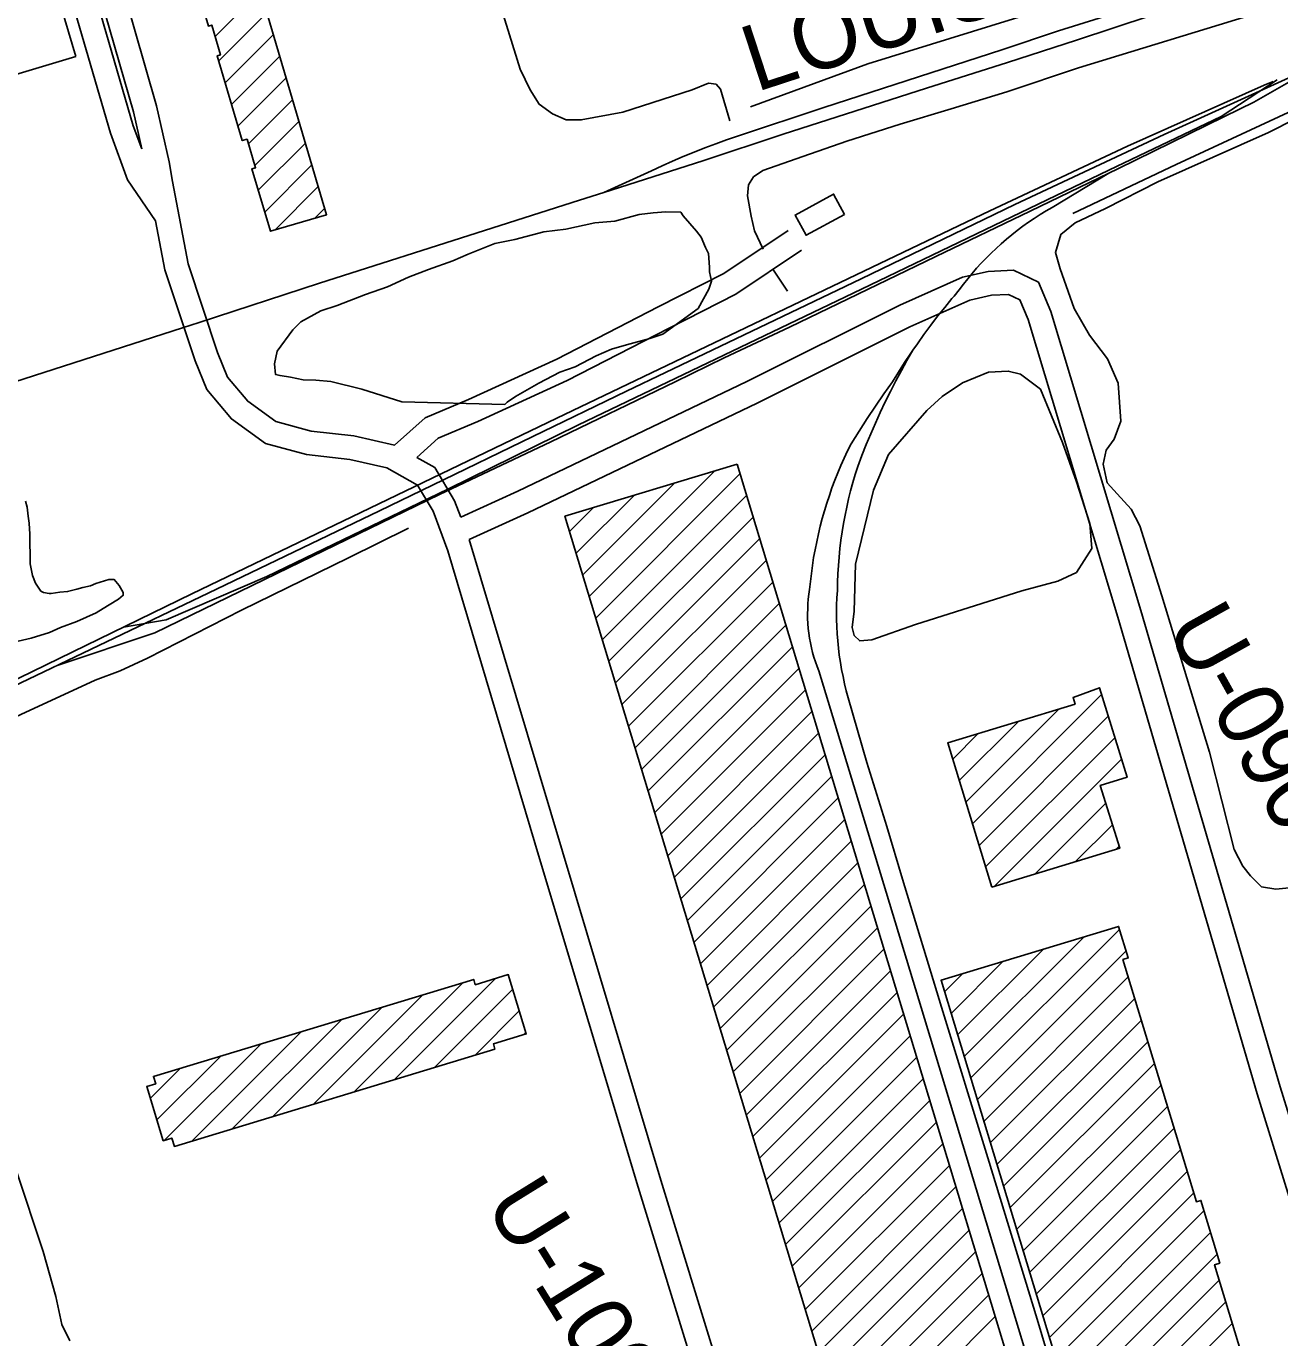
# Model space of a CAD drawing. Extents: x 3598634 to 3636690, y 517270 to 542944.
# Drawn here: x 3608299 to 3609873, y 535647 to 537294 of the extents above; entities that cross this region are included whole.
import ezdxf

# ---------------------------------------------------------------- set-up
doc = ezdxf.new("R2010")
doc.units = 0
for name, color, linetype in [('V-BLDG-OTLN', 7, 'Continuous'), ('V-RAIL-IDEN', 7, 'Continuous'), ('V-RAIL-TRAK', 7, 'Continuous'), ('V-RIVR-RANG-IDEN', 7, 'Continuous'), ('V-ROAD-CNTR', 7, 'Continuous'), ('V-SITE-VEGE', 7, 'Continuous'), ('V-TOPO-SHOR', 7, 'Continuous')]:
    doc.layers.add(name, color=color, linetype=linetype)

msp = doc.modelspace()

# ---------------------------------------------------------------- linework, layer by layer
at = {"layer": 'V-BLDG-OTLN'}
for p, q in [((3608536.4, 537281.6), (3608593.5, 537338.7)), ((3608541, 537250.8), (3608601.6, 537311.4)), ((3608549.1, 537223.5), (3608609.6, 537284.1)), ((3608557.1, 537196.2), (3608617.7, 537256.8)), ((3608565.2, 537168.9), (3608625.7, 537229.5)), ((3608578.3, 537146.8), (3608633.8, 537202.2)), ((3608586.4, 537119.5), (3608641.8, 537174.9)), ((3608590.7, 537088.4), (3608649.9, 537147.6)), ((3608598.8, 537061.1), (3608657.9, 537120.3)), ((3608611.5, 537038.5), (3608666, 537093)), ((3608661.6, 537053.3), (3608674, 537065.7)), ((3609006.2, 536578.3), (3609163.8, 536735.9)), ((3609014.4, 536551.1), (3609195.4, 536732.1)), ((3608989.8, 536632.6), (3609062.4, 536705.2)), ((3608998, 536605.4), (3609113.1, 536720.5)), ((3609022.7, 536524), (3609203.7, 536705)), ((3608981.6, 536659.7), (3609011.7, 536689.8)), ((3609030.9, 536496.9), (3609211.9, 536677.9)), ((3609039.1, 536469.7), (3609220.1, 536650.7)), ((3609047.3, 536442.6), (3609228.3, 536623.6)), ((3609055.5, 536415.5), (3609236.5, 536596.4)), ((3609063.7, 536388.3), (3609244.7, 536569.3)), ((3609072, 536361.2), (3609253, 536542.2)), ((3609080.2, 536334), (3609261.2, 536515)), ((3609088.4, 536306.9), (3609269.4, 536487.9)), ((3609096.6, 536279.8), (3609277.6, 536460.8)), ((3609487.3, 536292.7), (3609649.4, 536454.9)), ((3609104.8, 536252.6), (3609285.8, 536433.6)), ((3609479, 536319.8), (3609596.2, 536437)), ((3609495.5, 536265.6), (3609657.8, 536427.9)), ((3609470.8, 536346.9), (3609545.4, 536421.5)), ((3609113.1, 536225.5), (3609294, 536406.5)), ((3609462.5, 536374), (3609494.5, 536406)), ((3609503.8, 536238.5), (3609666.1, 536400.8)), ((3609121.3, 536198.4), (3609302.3, 536379.3)), ((3609514.5, 536213.9), (3609674.4, 536373.8)), ((3609129.5, 536171.2), (3609310.5, 536352.2)), ((3609137.7, 536144.1), (3609318.7, 536325.1)), ((3609565.4, 536229.4), (3609654.6, 536318.7)), ((3609145.9, 536116.9), (3609326.9, 536297.9)), ((3609616.2, 536244.9), (3609662.9, 536291.6)), ((3609154.1, 536089.8), (3609335.1, 536270.8)), ((3609667.1, 536260.4), (3609671.3, 536264.6)), ((3609162.4, 536062.7), (3609343.3, 536243.7)), ((3609170.6, 536035.5), (3609351.6, 536216.5)), ((3609178.8, 536008.4), (3609359.8, 536189.4)), ((3609187, 535981.2), (3609368, 536162.2)), ((3609476.8, 536000.3), (3609626.9, 536150.4)), ((3609485, 535973.2), (3609671.9, 536160.1)), ((3609195.2, 535954.1), (3609376.2, 536135.1)), ((3609468.6, 536027.5), (3609576.2, 536135)), ((3609493.3, 535946.1), (3609680.2, 536133)), ((3609460.4, 536054.6), (3609525.4, 536119.6)), ((3608761.2, 535971.2), (3608888.3, 536098.2)), ((3609203.4, 535927), (3609384.4, 536108)), ((3609452.1, 536081.7), (3609474.7, 536104.3)), ((3609501.5, 535918.9), (3609682.8, 536100.3)), ((3608710.5, 535955.7), (3608848.1, 536093.4)), ((3608812, 535986.6), (3608910.2, 536084.8)), ((3609211.7, 535899.8), (3609392.6, 536080.8)), ((3608608.9, 535924.9), (3608746.6, 536062.6)), ((3608659.7, 535940.3), (3608797.3, 536078)), ((3609509.7, 535891.8), (3609691.1, 536073.1)), ((3608558.1, 535909.5), (3608695.8, 536047.1)), ((3608862.8, 536002), (3608918.4, 536057.6)), ((3609219.9, 535872.7), (3609400.9, 536053.7)), ((3609517.9, 535864.7), (3609699.3, 536046)), ((3608507.4, 535894.1), (3608645, 536031.7)), ((3608924, 536027.9), (3608926.7, 536030.5)), ((3608473.1, 535895.2), (3608594.2, 536016.3)), ((3609228.1, 535845.6), (3609409.1, 536026.5)), ((3609526.2, 535837.5), (3609707.5, 536018.9)), ((3608463.4, 535920.8), (3608543.5, 536000.9)), ((3609236.3, 535818.4), (3609417.3, 535999.4)), ((3608455.2, 535947.9), (3608492.7, 535985.5)), ((3609534.4, 535810.4), (3609715.7, 535991.7)), ((3609244.5, 535791.3), (3609425.5, 535972.3)), ((3609542.6, 535783.3), (3609724, 535964.6)), ((3609252.7, 535764.1), (3609433.7, 535945.1)), ((3609550.9, 535756.2), (3609732.2, 535937.5)), ((3609261, 535737), (3609442, 535918)), ((3609559.1, 535729), (3609740.4, 535910.4)), ((3609269.2, 535709.9), (3609450.2, 535890.9)), ((3609567.3, 535701.9), (3609748.6, 535883.2)), ((3609277.4, 535682.7), (3609458.4, 535863.7)), ((3609575.5, 535674.8), (3609756.9, 535856.1)), ((3609285.6, 535655.6), (3609466.6, 535836.6)), ((3609583.8, 535647.6), (3609765.1, 535829)), ((3609293.8, 535628.5), (3609474.8, 535809.4)), ((3609592, 535620.5), (3609777.9, 535806.5)), ((3609302.1, 535601.3), (3609483, 535782.3)), ((3609600.2, 535593.4), (3609786.2, 535779.4)), ((3609310.3, 535574.2), (3609491.3, 535755.2)), ((3609608.4, 535566.2), (3609794.4, 535752.2)), ((3609318.5, 535547), (3609499.5, 535728)), ((3609616.7, 535539.1), (3609797, 535719.5)), ((3609326.7, 535519.9), (3609507.7, 535700.9)), ((3609624.9, 535512), (3609805.3, 535692.4)), ((3609334.9, 535492.8), (3609515.9, 535673.8)), ((3609633.1, 535484.9), (3609813.5, 535665.2))]:
    msp.add_line(p, q, dxfattribs=at)
for points in [[(3608721.3, 537478.3), (3608557, 537429.9), (3608573.8, 537373.1), (3608582.6, 537375.7), (3608676.4, 537057.6), (3608605.9, 537036.9), (3608582.7, 537115.5), (3608587.2, 537116.8), (3608576.6, 537152.6), (3608570.5, 537150.8), (3608539.1, 537257.3), (3608543.2, 537258.5), (3608532.2, 537295.9), (3608528, 537294.7), (3608493.8, 537410.6), (3608511.1, 537415.7), (3608488.5, 537492.2), (3608533.9, 537505.6), (3608534.7, 537503), (3608632.8, 537532), (3608631.7, 537535.7), (3608697.3, 537555.1)], [(3608361.5, 537256.3), (3608179.9, 537202), (3608146.2, 537314.8), (3608328.2, 537369.3)], [(3609326.7, 537058.2), (3609278.4, 537031.9), (3609264.6, 537057.3), (3609312.9, 537083.6)], [(3609191.7, 536744.3), (3609664, 535184.5), (3609504.1, 535136.1), (3609507.4, 535125.2), (3609451.4, 535108.2), (3608975.7, 536678.9)], [(3609511.5, 536213), (3609456.3, 536394.4), (3609616.2, 536443.1), (3609613.7, 536451.2), (3609646.8, 536463.6), (3609681.3, 536351.2), (3609647.8, 536340.9), (3609672.1, 536261.9)], [(3609679.8, 535330.8), (3609447.8, 536096.1), (3609670.8, 536163.7), (3609682.8, 536124.2), (3609676.2, 536122.1), (3609768.4, 535818), (3609774, 535819.7), (3609797.8, 535740.9), (3609791.2, 535738.9), (3609883.3, 535435.1), (3609890.8, 535437.4), (3609902.6, 535398.4)], [(3608887.8, 536009.6), (3608485.3, 535887.4), (3608482.1, 535897.9), (3608471.3, 535894.6), (3608450.7, 535962.7), (3608461.9, 535966.1), (3608459.1, 535975.3), (3608861.1, 536097.3), (3608863.1, 536090.6), (3608904.6, 536103.2), (3608927.2, 536028.8), (3608885.8, 536016.3)]]:
    msp.add_lwpolyline(points, close=True, dxfattribs=at)
at = {"layer": 'V-RAIL-TRAK'}
msp.add_line((3608460.7, 536532.7), (3608338.3, 536491.5), dxfattribs=at)
for points in [[(3610924.1, 537713.7), (3610829.6, 537683.4), (3610737.3, 537652.6), (3610625.8, 537616.9), (3610545, 537591.8), (3610461, 537564.4), (3610365.1, 537534.2), (3610269.6, 537504), (3610199.8, 537481.3), (3610125.8, 537457.3), (3610058.6, 537436.3), (3610002.5, 537418.3), (3609940.8, 537398.1), (3609859, 537372), (3609766.8, 537343.1), (3609697.4, 537320.4), (3609595.1, 537288.5), (3609524.3, 537264.9)], [(3609531.1, 537248.9), (3609617.9, 537277.1), (3609711.6, 537307.8), (3609811.1, 537339.3), (3609899.7, 537367.4), (3609988.8, 537396.9), (3610094.7, 537430), (3610186.1, 537460.3), (3610286.5, 537491.8), (3610401.6, 537528.8), (3610501.6, 537560.7), (3610590.3, 537589.3), (3610676.1, 537617), (3610722.7, 537632.2), (3610795.8, 537655.3), (3610884.4, 537684.3), (3610934.6, 537699.8)], [(3609524.3, 537264.9), (3609300.5, 537192.4), (3609192.5, 537156.5), (3609178.7, 537151.8), (3609164.9, 537146.9), (3609151.3, 537141.8), (3609137.7, 537136.4), (3609124.3, 537130.9), (3609110.9, 537125.1), (3609097.6, 537119.1), (3609084.4, 537112.9), (3609024.7, 537085.7)], [(3606956.3, 536421.4), (3607122.2, 536474.5), (3607344.5, 536544.9), (3607598.3, 536627.1), (3607814.4, 536696.1), (3608008.2, 536759), (3608234, 536831.4), (3608495.5, 536915.7), (3608516.5, 536922.5), (3608667.6, 536971.6), (3608874.7, 537037.9), (3608993.9, 537075.8), (3609024.7, 537085.7), (3609148.6, 537125.5), (3609249.7, 537158.7), (3609429.6, 537216.7), (3609531.1, 537248.9)], [(3608460.7, 536532.7), (3608628.8, 536614.4), (3608818.3, 536706.1), (3608957.8, 536772.6), (3609114, 536848), (3609175.4, 536877.8), (3609257.7, 536916.6), (3609343.5, 536958.1), (3609441.1, 537005.2), (3609559.7, 537062), (3609658.4, 537109.8), (3609669.9, 537115.3), (3609803.8, 537181.1), (3609840.7, 537199.1), (3609928.4, 537249.4)], [(3609921.3, 537246.5), (3609728.1, 537158.6), (3609540.6, 537070.7), (3609347.4, 536977.2), (3609101.9, 536859.5), (3609053.1, 536836), (3608935.2, 536779.2), (3608809.6, 536718.2), (3608742.7, 536685.7), (3608527.9, 536582.5), (3608272.6, 536460), (3608132.5, 536392.8), (3608062, 536358.2), (3607958.1, 536308.4), (3607754.5, 536210.7), (3607670.8, 536169.9), (3607478.3, 536077.1), (3607353.4, 536016.9), (3607237.7, 535961.5), (3607167.2, 535928.3), (3607022.2, 535858.3), (3606898, 535798.8)], [(3609658.4, 537109.8), (3609587.2, 537066.8), (3609579.7, 537062.4), (3609572.2, 537057.9), (3609564.9, 537053.1), (3609557.7, 537048.3), (3609550.5, 537043.2), (3609543.6, 537038), (3609536.7, 537032.6), (3609530, 537027), (3609523.4, 537021.3), (3609516.9, 537015.4), (3609510.6, 537009.4), (3609504.4, 537003.2), (3609498.4, 536996.9), (3609492.5, 536990.5), (3609486.8, 536983.9), (3609481.3, 536977.2), (3609475.9, 536970.3), (3609470.6, 536963.3), (3609464.2, 536955.6), (3609461.4, 536952.4), (3609452.4, 536941.3), (3609443.6, 536930.1), (3609434.9, 536918.8), (3609426.4, 536907.3), (3609418.1, 536895.7), (3609412.4, 536887.5), (3609410, 536883.9), (3609402, 536872.1), (3609394.3, 536860.1), (3609386.7, 536848), (3609376, 536832.7), (3609365.4, 536817.2), (3609355, 536801.7), (3609344.9, 536785.9), (3609335, 536770.1), (3609330.5, 536761.1), (3609326.2, 536751.9), (3609322.1, 536742.7), (3609318.2, 536733.5), (3609314.5, 536724.1), (3609310.9, 536714.7), (3609307.6, 536705.1), (3609304.5, 536695.6), (3609301.5, 536685.9), (3609298.7, 536676.2), (3609296.2, 536666.5), (3609293.8, 536656.7), (3609291.7, 536646.9), (3609289.7, 536637), (3609287.9, 536627.1), (3609286.4, 536617.1), (3609285, 536607.1), (3609283.9, 536597.1), (3609282.9, 536587.1), (3609282, 536581), (3609281.2, 536574.9), (3609280.7, 536568.8), (3609280.4, 536562.7), (3609280.3, 536556.5)], [(3609624.5, 535482.2), (3609568.6, 535670.4), (3609506.5, 535873.3), (3609448.6, 536062.2), (3609399.6, 536223.2), (3609379.6, 536289.4), (3609354.7, 536369.6), (3609331.3, 536451.1), (3609328.9, 536459.9), (3609326.7, 536468.7), (3609324.8, 536477.5), (3609323, 536486.4), (3609321.5, 536495.3), (3609320.1, 536504.3), (3609319, 536513.3), (3609318.1, 536522.3), (3609317.4, 536531.3), (3609316.9, 536540.3), (3609316.7, 536549.4), (3609316.6, 536558.4), (3609316.8, 536567.5), (3609317.1, 536576.6), (3609317.7, 536585.6), (3609317.9, 536596.2), (3609318.3, 536606.7), (3609319, 536617.3), (3609319.8, 536627.8), (3609320.9, 536638.3), (3609322.2, 536648.8), (3609323.6, 536659.3), (3609325.4, 536669.8), (3609327.3, 536680.2), (3609329.4, 536690.5), (3609331.8, 536700.8), (3609334.3, 536711.1), (3609337.1, 536721.3), (3609340.1, 536731.4), (3609343.2, 536741.5), (3609348.5, 536755.3), (3609353.9, 536768.9), (3609359.6, 536782.5), (3609365.4, 536796), (3609371.5, 536809.4), (3609377.8, 536822.7), (3609384.3, 536835.8), (3609391, 536848.9), (3609398, 536861.9), (3609405.1, 536874.7), (3609412.4, 536887.5)], [(3609280.3, 536556.5), (3609280.3, 536550.4), (3609280.6, 536544.2), (3609281.1, 536538.1), (3609281.8, 536532), (3609282.7, 536525.9), (3609283.8, 536519.9), (3609285.1, 536513.9), (3609286.6, 536507.9), (3609288.2, 536502), (3609290.1, 536496.2), (3609292.2, 536490.4), (3609294.5, 536484.7), (3609364.8, 536253.9), (3609471.1, 535903.3), (3609582.9, 535534.6), (3609634.6, 535348.5)]]:
    msp.add_lwpolyline(points, dxfattribs=at)
at = {"layer": 'V-ROAD-CNTR'}
for points in [[(3608444.5, 537140.3), (3608433.8, 537169.3), (3608389.5, 537320.7), (3608346.3, 537461.6), (3608328.8, 537514.7), (3608300.9, 537597.6)], [(3608444.5, 537140.3), (3608433.9, 537186.9), (3608392.7, 537331), (3608348.7, 537474.3), (3608333.4, 537532.2), (3608313.9, 537602.2)], [(3608761.9, 536768.2), (3608710.6, 536779.9), (3608656.9, 536786), (3608612.8, 536798), (3608577.4, 536823.5), (3608551.9, 536853.8), (3608539.5, 536884.7), (3608502.5, 536996.1), (3608483, 537099.6), (3608478.9, 537124), (3608463, 537194.3), (3608421.5, 537339.5), (3608377.5, 537482.5), (3608362.4, 537540.1), (3608342.8, 537610.3)], [(3608461.8, 537050), (3608426.7, 537101.6), (3608405.3, 537160), (3608360.8, 537312.1), (3608317.7, 537452.5), (3608300.3, 537505.2), (3608272.5, 537588)], [(3606905.8, 535810.9), (3607263.6, 535982.8), (3607637.6, 536162.7), (3608057, 536362.3), (3608507.4, 536581.5), (3608965.5, 536802), (3609509, 537062.7), (3609682.1, 537143.8), (3609853.7, 537220.3), (3609865, 537225.1)], [(3608421.5, 536539.7), (3608475, 536549), (3608601.3, 536603.2), (3608828.7, 536713.2), (3608992.6, 536793.8), (3609348, 536964.2), (3609658.4, 537113.8), (3609799.7, 537181), (3609870, 537227.3)], [(3609365.1, 534879.4), (3609322.3, 534996.3), (3609214, 535359.9), (3609067.4, 535836.2), (3608943.7, 536249.2), (3608828.6, 536635.4), (3608810.1, 536685.3), (3608790.5, 536718.1), (3608752, 536739.7), (3608705.6, 536750.3), (3608651.2, 536756.5), (3608599.7, 536770.5), (3608556.9, 536801.3), (3608525.9, 536838.1), (3608511.3, 536874.3), (3608473.4, 536988.6), (3608461.8, 537050)], [(3608761.9, 536768.2), (3608800.1, 536802.8), (3608854.4, 536825.6), (3608965.4, 536876.4), (3609092.8, 536941.9), (3609175, 536983.8), (3609256.1, 537038)], [(3608789.7, 536752.9), (3608816.4, 536777.1), (3608866.4, 536798.1), (3608978.5, 536849.4), (3609106.5, 536915.2), (3609190.2, 536957.9), (3609272.7, 537013.1)], [(3610034.7, 535467.5), (3610003.2, 535543.5), (3609873.5, 535962.3), (3609698.5, 536560.8), (3609585.6, 536936.2), (3609570, 536972.8), (3609539, 536988), (3609507.1, 536986.4), (3609474.6, 536979.1), (3609395.9, 536944.3), (3609204, 536848.1), (3608916.4, 536710.5), (3608844.8, 536677.9)], [(3610007, 535456), (3609974.9, 535533.3), (3609844.8, 535953.7), (3609669.8, 536552.2), (3609557.4, 536926), (3609546.8, 536950.7), (3609532.7, 536957.7), (3609511.2, 536956.6), (3609484, 536950.5), (3609408.7, 536917.1), (3609217.2, 536821.1), (3608929.1, 536683.3), (3608855.6, 536649.8)], [(3608844.8, 536677.9), (3608837.2, 536698.3), (3608812.2, 536740.4), (3608789.7, 536752.9)], [(3609393.3, 534889.8), (3609350.8, 535005.7), (3609242.7, 535368.6), (3609096.1, 535845), (3608972.5, 536257.8), (3608855.6, 536649.8)]]:
    msp.add_lwpolyline(points, dxfattribs=at)
at = {"layer": 'V-SITE-VEGE'}
for points in [[(3609896.9, 536213.4), (3609868, 536210.7), (3609850.2, 536213.5), (3609836.5, 536227.3), (3609826.9, 536239.6), (3609816, 536260.3), (3609784.7, 536382.6), (3609724.9, 536579.1), (3609697.6, 536667.1), (3609686.7, 536687.7), (3609668.9, 536707), (3609656.6, 536720.8), (3609651.2, 536744.2), (3609655.3, 536762), (3609665, 536775.7), (3609673.4, 536798.4), (3609670.2, 536846.1), (3609657, 536876.6), (3609634.3, 536906.6), (3609615, 536939.9), (3609597.4, 536989.8), (3609591.4, 537010.3), (3609598.1, 537033), (3609616.4, 537047.4), (3609654.2, 537065.6), (3609720.2, 537099.2), (3609858.9, 537160.9), (3609926.1, 537195)], [(3608298.6, 536698.1), (3608300.7, 536690.6), (3608301.6, 536678.9), (3608303, 536670.1), (3608303.9, 536656.4), (3608304.3, 536619.4), (3608307.2, 536604.4), (3608310.8, 536594.9), (3608317.7, 536584.7), (3608321.2, 536583.4), (3608328, 536582.1), (3608330.8, 536582.1), (3608341.7, 536583.6), (3608351.3, 536584.4), (3608362.9, 536587.3), (3608370.4, 536589.4), (3608379.9, 536591.6), (3608386.7, 536594.4), (3608403.1, 536599.4), (3608409.9, 536599.5), (3608416.2, 536592.1), (3608421.1, 536583.2), (3608421.1, 536579.8), (3608415, 536574.9), (3608403.5, 536567.9), (3608396, 536563.1), (3608387.2, 536557.5), (3608362.7, 536546.9), (3608342.2, 536539.2), (3608328.6, 536532.8), (3608305.5, 536525.7), (3608289.1, 536522.1)], [(3608286.7, 535857.8), (3608320.8, 535755.4), (3608336.4, 535699.1), (3608343.9, 535664), (3608354.1, 535643.4)]]:
    msp.add_lwpolyline(points, dxfattribs=at)
for points in [[(3608771, 536822.8), (3608720.6, 536838.5), (3608681.7, 536848.2), (3608662.8, 536850.1), (3608646.9, 536850.5), (3608631, 536853.8), (3608618, 536855.6), (3608612.2, 536857.2), (3608611.1, 536870.3), (3608614.4, 536886.2), (3608633.9, 536913.3), (3608644.3, 536923.2), (3608669.4, 536937.1), (3608689.9, 536943.8), (3608725.1, 536957.5), (3608752.9, 536967), (3608779.3, 536979.4), (3608804.2, 536988.9), (3608835, 536999.7), (3608854.1, 537008), (3608887.8, 537021.6), (3608912.6, 537026.8), (3608949.2, 537036.1), (3608976.9, 537039.7), (3609013.4, 537047.5), (3609038.1, 537049.8), (3609068.8, 537057.8), (3609086.3, 537060.2), (3609102.3, 537061.3), (3609121.1, 537060.8), (3609123.9, 537056.4), (3609140.9, 537037.1), (3609146.5, 537029.7), (3609152, 537016.5), (3609156.1, 537009.1), (3609157.1, 536991.7), (3609157, 536985.9), (3609159.6, 536974.2), (3609156.5, 536964.1), (3609142.8, 536939.8), (3609098.4, 536907.5), (3609082.3, 536902.1), (3609053.1, 536894.1), (3609034.1, 536888.8), (3609015, 536880.5), (3608988.5, 536866.7), (3608969.4, 536859.9), (3608943, 536846), (3608925.3, 536836.3), (3608913.5, 536829.3), (3608903.2, 536822.3), (3608900.2, 536819.5)], [(3609618.1, 536722.3), (3609634.5, 536670), (3609637.1, 536638.4), (3609617.8, 536608.3), (3609594.4, 536597.4), (3609549.1, 536585.1), (3609415.8, 536542.9), (3609360.8, 536523.9), (3609345.7, 536522.5), (3609338.8, 536529.4), (3609336.1, 536539.1), (3609338.9, 536559.6), (3609340.4, 536618.7), (3609362.9, 536711.7), (3609381.8, 536756.6), (3609430.2, 536811.8), (3609449.1, 536829.5), (3609474.6, 536846.6), (3609507.4, 536859.8), (3609532.3, 536861.4), (3609547.8, 536857.5), (3609572.7, 536838.6), (3609600.2, 536771.5)]]:
    msp.add_lwpolyline(points, close=True, dxfattribs=at)
at = {"layer": 'V-TOPO-SHOR'}
for p, q in [((3609355.9, 537247.1), (3609208.8, 537193.2)), ((3609255.2, 536961.5), (3609236.5, 536989.4))]:
    msp.add_line(p, q, dxfattribs=at)
for points in [[(3608919.4, 537240.4), (3608859.9, 537432.1), (3608839.1, 537503.3), (3608811.1, 537581), (3608803.7, 537612), (3608807, 537634.6), (3608813.8, 537653.4), (3608820.6, 537671.4), (3608826.9, 537692.4)], [(3609355.9, 537247.1), (3609641.8, 537336), (3609827.2, 537393.8), (3610000.6, 537445.6), (3610217, 537512.7), (3610323, 537546.3), (3610491.9, 537598.2), (3610601.5, 537632.6), (3610633.4, 537640), (3610676.3, 537653.4), (3610717.5, 537668.7), (3610733, 537674.6)], [(3609620.4, 537242.3), (3609847.8, 537311.8), (3610032.2, 537367.8), (3610172.8, 537412.3), (3610322.7, 537462), (3610444.2, 537502.5), (3610581.2, 537548), (3610689.1, 537585.1), (3610821.5, 537628), (3610927.5, 537662.5)], [(3609182.7, 537175.5), (3609171, 537215.3), (3609165.4, 537221.5), (3609155.7, 537223), (3609135.5, 537214.7), (3609048.3, 537186.4), (3608996.1, 537176.8), (3608977.3, 537176.8), (3608959.9, 537184.5), (3608943.2, 537196.4), (3608932.1, 537214.5), (3608919.4, 537240.4)], [(3609224.7, 537014.5), (3609213.7, 537037.5), (3609209.5, 537055.7), (3609204.7, 537081.4), (3609206.2, 537095.4), (3609212.5, 537105.1), (3609224.3, 537113.4), (3609274.5, 537130.7), (3609329.6, 537150), (3609396.5, 537171.4), (3609460.6, 537190.8), (3609530.3, 537212.1), (3609620.4, 537242.3)], [(3609613.5, 537059.4), (3609743.2, 537121), (3609977.5, 537229.7)], [(3607286.3, 535955.8), (3607330.9, 535975.9), (3607508.7, 536059), (3607692.8, 536146.2), (3607952.3, 536273.6), (3608111.3, 536344.9), (3608292.6, 536430.1), (3608386, 536473), (3608417.4, 536484.7), (3608451.6, 536500.6), (3608569.5, 536560.9), (3608704.1, 536626.7), (3608779.4, 536664.1)]]:
    msp.add_lwpolyline(points, dxfattribs=at)

# ---------------------------------------------------------------- texts
at = {"layer": 'V-RAIL-IDEN'}
msp.add_text('LOUISIANA', height=83, rotation=18.1286, dxfattribs=at).set_placement((3609215.4, 537211.4))
at = {"layer": 'V-RIVR-RANG-IDEN'}
for s, rotation, p in [('U-090', 299.1293, (3609728.8, 536539.6)), ('U-100', 301.7453, (3608873.8, 535815))]:
    msp.add_text(s, height=83, rotation=rotation, dxfattribs=at).set_placement(p)

doc.saveas('drawing.dxf')
